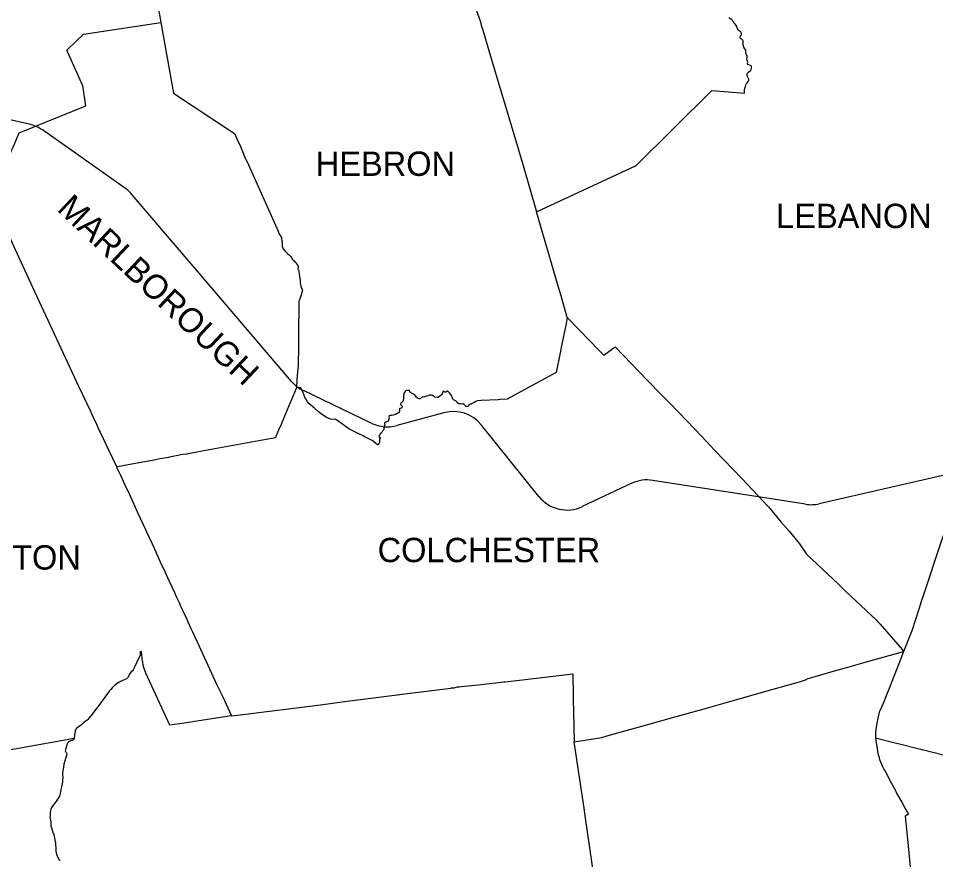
# Model space of a CAD drawing. Extents: x 0 to 2603, y -226 to 830.
# Drawn here: x 236.4 to 287.2, y 575 to 621.7 of the extents above; entities that cross this region are included whole.
import ezdxf

# ---------------------------------------------------------------- set-up
doc = ezdxf.new("R2010")
doc.units = 0
for name, color, linetype in [('CT_TSH_Map_Districts', 7, 'Continuous'), ('CT_TSH_Map_Town_Limits', 7, 'Continuous'), ('CT_TSH_Map_Town_Text', 7, 'Continuous'), ('CT_TSH_Map_US_and_State_Routes', 7, 'Continuous')]:
    doc.layers.add(name, color=color, linetype=linetype)

msp = doc.modelspace()

# ---------------------------------------------------------------- linework, layer by layer
at = {"layer": 'CT_TSH_Map_Districts'}
for points in [[(242.829, 630.489), (243.048, 629.102), (243.244, 627.867), (243.357, 627.101), (243.509, 626.175), (243.519, 626.111), (243.576, 625.739), (244.001, 623.073), (244.135, 622.27), (244.272, 621.425)], [(234.884, 611.677), (235.041, 612.051), (235.566, 613.271), (235.579, 613.297), (235.927, 614.12), (235.983, 614.28), (236.084, 614.51), (236.428, 615.301), (240.127, 616.807), (239.953, 617.904), (239.072, 619.882), (239.607, 620.4), (239.988, 620.781), (244.272, 621.425)]]:
    msp.add_lwpolyline(points, dxfattribs=at)
at = {"layer": 'CT_TSH_Map_Town_Limits'}
for points in [[(242.829, 630.489), (243.048, 629.102), (243.244, 627.867), (243.357, 627.101), (243.509, 626.175), (243.519, 626.111), (243.576, 625.739), (244.001, 623.073), (244.135, 622.27), (244.272, 621.425)], [(260.833, 624.75), (262.008, 621.464), (262.05, 621.275), (262.135, 620.995), (262.754, 618.936), (263.599, 616.098), (264.382, 613.489), (265.122, 610.932)], [(265.122, 610.932), (270.613, 613.469), (270.631, 613.484), (274.841, 617.658), (276.652, 617.497), (276.645, 617.614), (276.647, 617.721), (276.666, 617.769), (276.69, 617.815), (276.699, 617.873), (276.723, 617.97), (276.762, 618.041), (276.795, 618.082), (276.844, 618.156), (276.881, 618.235), (276.883, 618.276), (276.869, 618.318), (276.816, 618.426), (276.796, 618.49), (276.797, 618.55), (276.822, 618.619), (276.87, 618.675), (276.988, 618.754), (277.018, 618.806), (277.036, 618.901), (277.029, 618.965), (277.011, 619.014), (276.972, 619.047), (276.837, 619.096), (276.809, 619.115), (276.812, 619.162), (276.827, 619.211), (276.823, 619.25), (276.806, 619.29), (276.772, 619.364), (276.791, 619.511), (276.789, 619.567), (276.766, 619.635), (276.737, 619.681), (276.724, 619.723), (276.723, 619.835), (276.714, 619.876), (276.613, 620.061), (276.588, 620.129), (276.58, 620.188), (276.582, 620.335), (276.574, 620.396), (276.549, 620.444), (276.494, 620.498), (276.435, 620.546), (276.408, 620.58), (276.399, 620.607), (276.4, 620.634), (276.423, 620.678), (276.451, 620.705), (276.48, 620.737), (276.483, 620.754), (276.473, 620.799), (276.462, 620.885), (276.454, 620.897), (276.431, 620.916), (276.365, 620.944), (276.317, 620.988), (276.247, 621.106), (276.216, 621.194), (276.19, 621.26), (276.157, 621.309), (276.081, 621.413), (276.034, 621.466), (276.005, 621.493), (275.996, 621.516), (275.979, 621.541), (275.951, 621.575), (275.892, 621.607), (275.772, 621.676)], [(234.884, 611.677), (235.041, 612.051), (235.566, 613.271), (235.579, 613.297), (235.927, 614.12), (235.983, 614.28), (236.084, 614.51), (236.428, 615.301), (240.127, 616.807), (239.953, 617.904), (239.072, 619.882), (239.607, 620.4), (239.988, 620.781), (244.272, 621.425)], [(244.272, 621.425), (244.975, 617.509), (248.365, 615.272), (248.57, 614.801), (248.654, 614.632), (248.963, 613.907), (248.999, 613.832), (249.06, 613.693), (250.79, 609.844), (250.814, 609.79), (250.833, 609.72), (250.902, 609.607), (250.921, 609.569), (250.956, 609.52), (250.992, 609.482), (251, 609.457), (250.967, 609.427), (250.962, 609.395), (250.999, 609.37), (251.013, 609.339), (250.998, 609.292), (250.994, 609.267), (251.009, 609.212), (251.017, 609.16), (251.008, 609.085), (251.013, 609), (251.021, 608.951), (251.061, 608.87), (251.183, 608.748), (251.233, 608.689), (251.342, 608.583), (251.401, 608.542), (251.485, 608.45), (251.52, 608.397), (251.542, 608.348), (251.571, 608.298), (251.62, 608.24), (251.673, 608.198), (251.72, 608.152), (251.772, 608.089), (251.871, 607.94), (251.893, 607.901), (251.904, 607.854), (251.902, 607.808), (251.871, 607.738), (251.897, 607.714), (251.915, 607.705), (251.93, 607.616), (251.944, 607.469), (251.998, 607.219), (252.006, 607.138), (252.004, 607.069), (252.014, 606.988), (252.031, 606.918), (252.05, 606.8), (252.069, 606.737), (252.143, 606.555), (252.002, 606.155), (251.955, 605.993), (251.937, 605.973), (251.93, 605.933), (251.911, 604.063), (251.911, 603.524), (251.899, 602.372), (251.88, 602.226), (251.868, 602.038), (251.85, 601.863), (251.799, 601.246), (251.802, 601.191)], [(234.884, 611.677), (234.922, 611.605), (234.945, 611.566), (235.077, 611.27), (235.998, 609.281), (237.269, 606.502), (239.719, 601.253), (240.373, 599.873), (240.571, 599.445), (240.652, 599.27), (240.867, 598.805), (240.916, 598.702), (241.403, 597.685), (241.795, 596.836), (241.83, 596.77)], [(266.823, 605.07), (266.474, 606.258), (266.379, 606.617), (265.122, 610.932)], [(266.823, 605.07), (266.759, 604.739), (266.676, 604.382), (266.517, 603.589), (266.409, 603.006), (266.213, 602.006), (265.596, 601.674), (264.706, 601.194), (264.272, 600.953), (263.491, 600.537), (263.1, 600.508), (262.996, 600.506), (262.04, 600.452), (261.847, 600.435), (261.758, 600.414), (261.654, 600.353), (261.528, 600.29), (261.487, 600.266), (261.435, 600.263), (261.36, 600.22), (261.336, 600.161), (261.308, 600.135), (261.272, 600.124), (261.24, 600.123), (261.196, 600.13), (261.173, 600.153), (261.153, 600.187), (261.108, 600.244), (261.073, 600.267), (261.025, 600.267), (260.978, 600.257), (260.886, 600.277), (260.806, 600.272), (260.764, 600.287), (260.715, 600.33), (260.695, 600.361), (260.677, 600.402), (260.655, 600.431), (260.628, 600.443), (260.597, 600.441), (260.576, 600.452), (260.563, 600.473), (260.544, 600.484), (260.518, 600.49), (260.492, 600.514), (260.477, 600.54), (260.436, 600.668), (260.419, 600.706), (260.391, 600.745), (260.365, 600.794), (260.281, 600.889), (260.215, 600.956), (260.188, 600.97), (260.153, 600.976), (260.137, 600.968), (260.086, 600.925), (260.057, 600.921), (260.037, 600.925), (259.979, 600.974), (259.962, 600.976), (259.937, 600.957), (259.921, 600.934), (259.89, 600.829), (259.874, 600.793), (259.848, 600.771), (259.815, 600.754), (259.79, 600.735), (259.751, 600.697), (259.678, 600.638), (259.654, 600.629), (259.596, 600.624), (259.484, 600.651), (259.458, 600.665), (259.344, 600.745), (259.284, 600.748), (259.216, 600.754), (259.178, 600.754), (259.146, 600.743), (259.1, 600.711), (258.994, 600.699), (258.919, 600.665), (258.898, 600.656), (258.822, 600.64), (258.787, 600.643), (258.764, 600.642), (258.737, 600.633), (258.705, 600.592), (258.68, 600.571), (258.655, 600.559), (258.613, 600.554), (258.521, 600.584), (258.43, 600.662), (258.413, 600.697), (258.359, 600.774), (258.33, 600.801), (258.3, 600.816), (258.264, 600.827), (258.225, 600.839), (258.212, 600.853), (258.097, 600.921), (258.088, 600.944)], [(266.823, 605.07), (267.456, 604.399), (268.63, 603.191), (268.844, 602.968), (269.479, 603.439), (271.293, 601.554), (272.026, 600.802), (272.437, 600.386), (273.026, 599.78), (274.267, 598.484), (275.012, 597.692), (276.494, 596.138), (277.693, 594.865), (277.868, 594.665), (277.973, 594.556), (278.431, 594.019), (278.663, 593.737), (279.121, 593.208), (279.701, 592.515), (280.092, 591.942), (281.856, 590.273), (282.234, 589.91), (283.967, 588.275), (284.03, 588.21), (284.174, 588.05), (285.389, 586.646), (285.469, 586.545)], [(251.802, 601.191), (251.806, 601.172), (251.794, 601.129), (251.599, 600.682), (251.386, 600.168), (251.003, 599.279), (250.948, 599.129), (250.814, 598.81), (250.667, 598.472), (250.634, 598.383), (250.543, 598.372), (250.115, 598.294), (247.063, 597.745), (245.78, 597.507), (245.731, 597.492), (245.5, 597.457), (244.763, 597.319), (244.705, 597.306), (244.239, 597.219), (243.804, 597.141), (243.074, 596.999), (243.057, 597.003), (241.886, 596.778), (241.83, 596.77)], [(253.353, 599.592), (253.333, 599.614), (253.306, 599.633), (253.168, 599.721), (253.006, 599.856), (252.811, 600.028), (252.483, 600.302), (252.407, 600.392), (252.316, 600.544), (252.274, 600.634), (252.206, 600.803), (252.165, 600.888), (252.063, 601.135), (252.053, 601.157), (252.039, 601.172), (251.802, 601.191)], [(258.088, 600.944), (258.069, 601.026), (258.031, 601.011), (257.896, 601.013), (257.864, 600.993), (257.828, 600.961), (257.779, 600.885), (257.765, 600.849), (257.763, 600.813), (257.758, 600.791), (257.74, 600.734), (257.731, 600.604), (257.73, 600.562), (257.715, 600.46), (257.695, 600.396), (257.677, 600.372), (257.618, 600.349), (257.593, 600.332), (257.581, 600.296), (257.58, 600.27), (257.599, 600.216), (257.648, 600.17), (257.661, 600.148), (257.66, 600.085), (257.646, 600.061), (257.627, 600.041), (257.542, 600.014), (257.525, 600.002), (257.517, 599.98), (257.518, 599.892), (257.51, 599.853), (257.5, 599.827), (257.458, 599.78), (257.384, 599.737), (257.343, 599.717), (257.3, 599.686), (257.158, 599.648), (257.1, 599.635), (256.992, 599.63), (256.936, 599.606), (256.925, 599.594), (256.937, 599.527), (256.931, 599.461), (256.921, 599.433), (256.911, 599.369), (256.88, 599.318), (256.841, 599.292), (256.753, 599.254), (256.721, 599.236), (256.692, 599.212), (256.686, 599.194), (256.686, 599.172), (256.702, 599.125), (256.702, 599.105), (256.666, 599.02), (256.651, 598.931), (256.655, 598.872), (256.629, 598.812), (256.61, 598.792), (256.576, 598.763), (256.551, 598.717), (256.476, 598.643), (256.431, 598.584), (256.418, 598.554), (256.392, 598.523), (256.373, 598.458), (256.381, 598.432), (256.395, 598.419), (256.437, 598.419), (256.447, 598.412), (256.455, 598.397), (256.452, 598.379), (256.416, 598.307), (256.411, 598.284), (256.416, 598.186), (256.407, 598.129), (256.395, 598.097), (256.341, 598.026), (256.304, 597.997), (256.299, 597.997), (256.078, 598.182), (255.994, 598.244), (255.926, 598.285), (255.708, 598.383), (255.61, 598.432), (255.503, 598.498), (255.265, 598.611), (254.713, 598.893), (254.502, 599.029), (254.448, 599.072), (254.296, 599.179), (254.162, 599.275), (254.101, 599.338), (254.048, 599.376), (253.985, 599.411), (253.958, 599.416), (253.908, 599.414), (253.714, 599.425), (253.595, 599.459), (253.45, 599.528), (253.353, 599.592)], [(289.803, 598.588), (289.688, 598.309), (288.801, 596.091), (288.352, 594.945), (288.276, 594.762), (287.754, 593.241), (287.72, 593.124), (287.551, 592.637), (286.557, 589.62), (286.471, 589.362), (286.336, 588.939), (285.92, 587.694), (285.563, 586.765), (285.469, 586.545)], [(241.83, 596.77), (242.041, 596.311), (242.271, 595.824), (242.535, 595.248), (242.779, 594.706), (242.988, 594.252), (243.424, 593.311), (243.49, 593.169), (243.794, 592.512), (244.001, 592.067), (244.023, 592.021), (244.247, 591.508), (244.503, 590.977), (244.558, 590.852), (244.746, 590.449), (245.039, 589.803), (245.138, 589.589), (245.183, 589.487), (245.313, 589.212), (245.352, 589.115), (245.458, 588.875), (245.719, 588.329), (245.797, 588.157), (245.972, 587.777), (246.041, 587.623), (246.391, 586.878), (247.391, 584.692), (247.714, 584.024), (248.089, 583.208), (248.194, 582.969)], [(267.208, 581.532), (268.746, 581.779), (269.084, 581.88), (271.281, 582.49), (272.862, 582.928), (273.681, 583.162), (274.533, 583.397), (276.606, 583.985), (277.57, 584.266), (279.702, 584.866), (280.08, 584.981), (280.132, 585.026), (281.648, 585.459), (282.128, 585.594), (283.423, 585.964), (285.469, 586.545)], [(285.469, 586.545), (285.325, 586.154), (285.237, 585.946), (284.788, 584.783), (284.667, 584.486), (284.582, 584.258), (284.339, 583.664), (284.148, 583.241), (284.12, 583.175), (284.072, 583.002), (284.016, 582.742), (283.953, 582.368), (283.917, 582.028), (283.915, 581.856), (283.917, 581.75)], [(248.194, 582.969), (246.391, 582.696), (245.581, 582.567), (244.781, 582.446), (243.455, 585.347), (243.336, 585.648), (243.303, 585.78), (243.274, 585.95), (243.275, 585.978), (243.273, 585.988), (243.204, 586.532), (243.15, 586.519), (243.125, 586.508), (243.155, 586.399), (243.136, 586.342), (242.929, 585.915), (242.818, 585.665), (242.748, 585.522), (242.706, 585.465), (242.681, 585.447), (242.555, 585.317), (242.526, 585.266), (242.517, 585.229), (242.459, 585.096), (242.434, 585.055), (242.416, 585.04), (242.343, 585.005), (242.244, 584.966), (241.978, 584.842), (241.888, 584.789), (241.751, 584.69), (241.575, 584.519), (241.504, 584.427), (241.442, 584.362), (241.03, 583.796), (240.841, 583.546), (240.622, 583.264), (240.481, 583.066), (240.305, 582.854), (240.228, 582.761), (240.19, 582.735), (240.068, 582.636), (239.939, 582.535), (239.86, 582.462), (239.716, 582.36), (239.589, 582.251), (239.563, 582.214), (239.537, 582.156), (239.522, 582.09), (239.505, 582.045), (239.476, 581.735), (239.476, 581.714)], [(248.194, 582.969), (248.683, 583.029), (253.136, 583.59), (254.475, 583.765), (255.066, 583.838), (258.104, 584.232), (260.364, 584.505), (260.395, 584.518), (260.481, 584.53), (260.547, 584.534), (260.652, 584.559), (260.717, 584.58), (260.831, 584.58), (260.934, 584.6), (261.878, 584.683), (262.649, 584.776), (262.863, 584.798), (263.301, 584.855), (263.396, 584.861), (267.121, 585.306), (267.122, 585.135), (267.127, 584.994), (267.125, 584.908), (267.147, 584.496), (267.153, 584.283), (267.142, 584.062), (267.149, 583.847), (267.172, 583.189), (267.208, 581.532)], [(239.476, 581.714), (236.384, 581.164), (236.063, 581.104), (234.377, 580.866), (232.933, 580.667), (232.367, 580.578), (230.098, 580.254), (229.204, 580.131), (228.737, 580.061), (227.594, 579.901), (227.127, 579.835), (226.889, 579.805), (226.593, 579.751), (226.349, 579.726)], [(239.476, 581.714), (239.477, 581.696), (239.451, 581.664), (239.42, 581.636), (239.347, 581.609), (239.196, 581.548), (239.148, 581.511), (239.116, 581.462), (239.095, 581.423), (239.01, 581.155), (238.979, 581.032), (238.989, 581.002), (239.011, 580.965), (239.052, 580.917), (239.07, 580.881), (239.045, 580.772), (239.006, 580.661), (238.906, 580.292), (238.875, 580.118), (238.836, 579.803), (238.831, 579.71), (238.837, 579.548), (238.826, 579.413), (238.823, 579.325), (238.81, 579.193), (238.781, 579.043), (238.744, 578.883), (238.724, 578.764), (238.679, 578.615), (238.654, 578.512), (238.595, 578.398), (238.452, 578.208), (238.379, 578.105), (238.25, 577.938), (238.192, 577.847), (238.176, 577.819), (238.166, 577.749), (238.146, 577.55), (238.139, 577.392), (238.133, 577.349), (238.167, 577.185), (238.174, 577.071), (238.174, 576.874), (238.293, 576.515), (238.342, 576.394), (238.411, 576.088), (238.431, 575.903), (238.433, 575.837), (238.453, 575.632), (238.461, 575.459), (238.478, 575.38), (238.515, 575.246), (238.621, 575.007), (238.691, 574.925)], [(270.379, 562.345), (270.039, 564.904), (269.59, 568.452), (269.414, 569.81), (269.325, 570.526), (269.124, 572.08), (269.095, 572.218), (268.612, 572.145), (268.366, 573.678), (268.222, 574.621), (268.17, 574.999), (268.05, 575.782), (267.832, 577.304), (267.758, 577.846), (267.665, 578.462), (267.208, 581.532)], [(283.917, 581.75), (285.013, 581.479), (285.092, 581.454), (286.411, 581.124), (286.459, 581.106), (286.642, 581.061), (288.26, 580.652)], [(283.917, 581.75), (283.943, 581.488), (283.979, 581.244), (284.051, 580.876), (284.091, 580.719), (284.114, 580.654), (284.142, 580.556), (284.302, 580.159), (284.397, 579.976), (284.441, 579.9), (284.778, 579.264), (285.018, 578.825), (285.087, 578.692), (285.367, 578.183), (285.518, 577.913), (285.736, 577.516), (285.564, 577.404), (285.727, 575.756), (285.877, 574.213)]]:
    msp.add_lwpolyline(points, dxfattribs=at)
at = {"layer": 'CT_TSH_Map_US_and_State_Routes'}
for p, q in [((236.999, 615.779), (233.962, 616.462)), ((242.325, 612.212), (237.711, 615.463)), ((255.984, 599.192), (252.186, 601.007)), ((259.975, 599.778), (257.373, 599.068)), ((265.247, 595.134), (262.061, 599.101)), ((288.303, 596.458), (280.795, 594.734)), ((270.407, 595.867), (267.655, 594.576)), ((280.038, 594.707), (271.565, 596.032))]:
    msp.add_line(p, q, dxfattribs=at)
msp.add_lwpolyline([(251.526, 601.515), (247.167, 606.629), (242.695, 611.874)], dxfattribs=at)
for centre, start, end in [((236.559, 613.828), 54.8301, 77.3197), ((241.173, 610.577), 40.4445, 54.8301), ((253.048, 602.812), 220.4445, 244.4599), ((260.501, 597.848), 38.7706, 105.2644), ((256.846, 600.997), 244.4599, 285.2644), ((271.256, 594.056), 81.1119, 115.1335), ((266.806, 596.387), 218.7706, 295.1335), ((280.347, 596.683), 261.1119, 282.9326)]:
    msp.add_arc(centre, 2, start, end, dxfattribs=at)

# ---------------------------------------------------------------- texts
at = {"layer": 'CT_TSH_Map_Town_Text'}
for s, p in [('HEBRON', (252.873, 612.918)), ('LEBANON', (278.402, 610.023)), ('COLCHESTER', (256.303, 591.494)), ('HAMPTON', (230.818, 591.083))]:
    msp.add_text(s, height=1.35, dxfattribs=at).set_placement(p)
msp.add_text('MARLBOROUGH', height=1.35, rotation=316.7753, dxfattribs=at).set_placement((238.468, 611.019))

doc.saveas('drawing.dxf')
